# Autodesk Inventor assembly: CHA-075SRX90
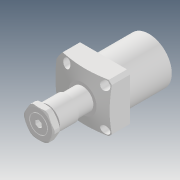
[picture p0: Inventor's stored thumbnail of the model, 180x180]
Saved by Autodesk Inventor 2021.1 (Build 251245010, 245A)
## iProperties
Created: 2019-05
Part Number: CHA-075SRX90
Description: STEP AP203
Document SubType Name: Assembly
Designer: user
Title: CHA-075SRX90.STEP
Revision Number: ÈÎºÎ
Sending System: SolidWorks 2017
Preprocessor: SwSTEP 2.0
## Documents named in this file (5)
- D:\Vault_2016\Projekty\Clamptek\Hydraulic\CHA\CHA\CHA-075\Inventor\CHA-075SRX90\CHA-075SRX90.iam
- D:\Vault_2016\Projekty\Clamptek\Hydraulic\CHA\CHA\CHA-075\Inventor\CHA-075SRX90\CHA-075±¾Ìå.ipt
- D:\Vault_2016\Projekty\Clamptek\Hydraulic\CHA\CHA\CHA-075\Inventor\CHA-075SRX90\CHA-075S×¶Ì×.ipt
- D:\Vault_2016\Projekty\Clamptek\Hydraulic\CHA\CHA\CHA-075\Inventor\CHA-075SRX90\CHA-075S»îÈû¸Ë.ipt
- D:\Vault_2016\Projekty\Clamptek\Hydraulic\CHA\CHA\CHA-075\Inventor\CHA-075SRX90\CHA-075ÂÝÄ¸.ipt
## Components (4 placed, 4 different names)
1. CHA-075±¾Ìå_1
2. CHA-075S×¶Ì×_2
3. CHA-075S»îÈû¸Ë_3
4. CHA-075ÂÝÄ¸_4
